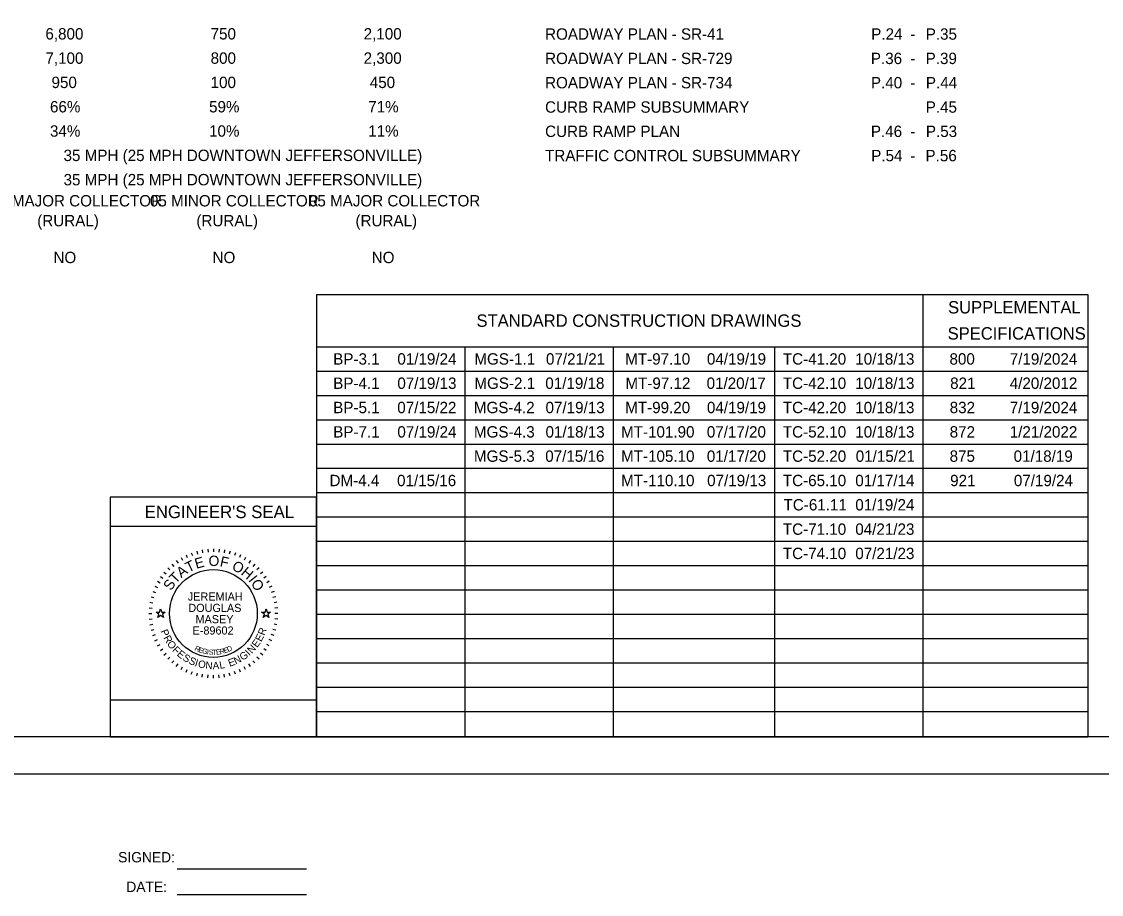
# Model space of a CAD drawing. Extents: x 0 to 34, y -1.6 to 22.
# Drawn here: x 7.84 to 22.48, y -1.63 to 10.19 of the extents above; entities that cross this region are included whole.
import ezdxf

# ---------------------------------------------------------------- set-up
doc = ezdxf.new("R2010")
doc.units = 0
for name, color, linetype in [('SH_Border', 7, 'Continuous'), ('SH_Cut_Line', 7, 'Continuous'), ('SH_Data', 7, 'Continuous'), ('SH_Text', 7, 'Continuous')]:
    doc.layers.add(name, color=color, linetype=linetype)

msp = doc.modelspace()

# ---------------------------------------------------------------- linework, layer by layer
at = {"layer": 'SH_Border'}
msp.add_lwpolyline([(1.5, 21.5), (33.5, 21.5), (33.5, 0.5), (1.5, 0.5)], close=True, dxfattribs=at)
at = {"layer": 'SH_Cut_Line'}
msp.add_lwpolyline([(0, 0), (34, 0), (34, 22), (0, 22)], close=True, dxfattribs=at)
at = {"layer": 'SH_Data'}
for p, q in [((11.844, 3.75), (9.044, 3.75)), ((9.044, 3.75), (9.044, 0.5)), ((11.844, 0.5), (11.844, 3.75)), ((11.844, 3.35), (9.044, 3.35)), ((10.007, 2.931), (10.027, 2.896)), ((10.075, 2.966), (10.091, 2.93)), ((10.145, 2.995), (10.159, 2.957)), ((10.218, 3.018), (10.228, 2.979)), ((10.292, 3.034), (10.299, 2.995)), ((10.368, 3.044), (10.372, 3.005)), ((10.444, 3.048), (10.444, 3.008)), ((10.521, 3.044), (10.517, 3.005)), ((10.596, 3.034), (10.589, 2.995)), ((10.671, 3.018), (10.66, 2.979)), ((10.744, 2.995), (10.73, 2.957)), ((10.814, 2.966), (10.797, 2.93)), ((10.882, 2.931), (10.862, 2.896)), ((9.826, 2.792), (9.854, 2.763)), ((9.882, 2.843), (9.908, 2.812)), ((9.942, 2.89), (9.965, 2.857)), ((10.946, 2.89), (10.923, 2.857)), ((11.007, 2.843), (10.981, 2.812)), ((11.063, 2.792), (11.035, 2.763)), ((9.728, 2.675), (9.76, 2.652)), ((9.774, 2.735), (9.805, 2.71)), ((11.115, 2.735), (11.084, 2.71)), ((11.161, 2.675), (11.128, 2.652)), ((9.651, 2.543), (9.688, 2.526)), ((9.687, 2.61), (9.721, 2.59)), ((11.202, 2.61), (11.168, 2.59)), ((11.237, 2.543), (11.201, 2.526)), ((9.599, 2.399), (9.638, 2.389)), ((9.622, 2.472), (9.66, 2.458)), ((11.267, 2.472), (11.229, 2.458)), ((11.29, 2.399), (11.251, 2.389)), ((9.573, 2.249), (9.613, 2.246)), ((9.583, 2.325), (9.622, 2.318)), ((11.306, 2.325), (11.267, 2.318)), ((11.316, 2.249), (11.276, 2.246)), ((9.569, 2.173), (9.609, 2.173)), ((9.573, 2.097), (9.613, 2.1)), ((11.316, 2.097), (11.276, 2.1)), ((11.319, 2.173), (11.279, 2.173)), ((9.583, 2.021), (9.622, 2.028)), ((9.599, 1.946), (9.638, 1.957)), ((11.29, 1.946), (11.251, 1.957)), ((11.306, 2.021), (11.267, 2.028)), ((9.622, 1.874), (9.66, 1.887)), ((9.651, 1.803), (9.688, 1.82)), ((11.237, 1.803), (11.201, 1.82)), ((11.267, 1.874), (11.229, 1.887)), ((9.687, 1.735), (9.721, 1.755)), ((9.728, 1.671), (9.76, 1.694)), ((9.774, 1.61), (9.805, 1.636)), ((11.115, 1.61), (11.084, 1.636)), ((11.161, 1.671), (11.128, 1.694)), ((11.202, 1.735), (11.168, 1.755)), ((9.826, 1.554), (9.854, 1.582)), ((9.882, 1.503), (9.908, 1.533)), ((9.942, 1.456), (9.965, 1.489)), ((10.946, 1.456), (10.923, 1.489)), ((11.007, 1.503), (10.981, 1.533)), ((11.063, 1.554), (11.035, 1.582)), ((10.007, 1.415), (10.027, 1.45)), ((10.075, 1.38), (10.091, 1.416)), ((10.145, 1.351), (10.159, 1.388)), ((10.218, 1.328), (10.228, 1.366)), ((10.292, 1.311), (10.299, 1.35)), ((10.368, 1.301), (10.372, 1.341)), ((10.444, 1.298), (10.444, 1.338)), ((10.521, 1.301), (10.517, 1.341)), ((10.596, 1.311), (10.589, 1.35)), ((10.671, 1.328), (10.66, 1.366)), ((10.744, 1.351), (10.73, 1.388)), ((10.814, 1.38), (10.797, 1.416)), ((10.882, 1.415), (10.862, 1.45)), ((11.844, 0.5), (9.044, 0.5))]:
    msp.add_line(p, q, dxfattribs=at)
msp.add_lwpolyline([(11.844, 0.5), (11.844, 1), (9.044, 1), (9.044, 0.5)], close=True, dxfattribs=at)
msp.add_circle((10.444, 2.173), 0.595, dxfattribs=at)
at = {"layer": 'SH_Text'}
for p, q in [((11.844, 6.495), (22.303, 6.495)), ((11.844, 6.495), (11.844, 0.5)), ((20.063, 6.495), (20.063, 0.5)), ((22.303, 6.495), (22.303, 0.5)), ((11.844, 5.787), (22.303, 5.787)), ((13.854, 5.787), (13.854, 0.5)), ((15.863, 5.787), (15.863, 0.5)), ((18.054, 5.787), (18.054, 0.5)), ((11.844, 5.458), (22.303, 5.458)), ((11.844, 5.128), (22.303, 5.128)), ((11.844, 4.799), (22.303, 4.799)), ((11.844, 4.469), (22.303, 4.469)), ((11.844, 4.14), (22.303, 4.14)), ((11.844, 3.811), (22.303, 3.811)), ((11.844, 3.481), (22.303, 3.481)), ((11.844, 3.152), (22.303, 3.152)), ((11.844, 2.822), (22.303, 2.822)), ((11.844, 2.493), (22.303, 2.493)), ((11.844, 2.164), (22.303, 2.164)), ((11.844, 1.834), (22.303, 1.834)), ((11.844, 1.505), (22.303, 1.505)), ((11.844, 1.175), (22.303, 1.175)), ((11.844, 0.846), (22.303, 0.846)), ((11.844, 0.5), (22.303, 0.5)), ((9.955, -1.286), (11.705, -1.286)), ((9.955, -1.633), (11.705, -1.633))]:
    msp.add_line(p, q, dxfattribs=at)
for points in [[(9.668, 2.193), (9.715, 2.193), (9.729, 2.237), (9.744, 2.193), (9.791, 2.193), (9.753, 2.165), (9.767, 2.121), (9.729, 2.148), (9.691, 2.121), (9.706, 2.165)], [(11.098, 2.193), (11.145, 2.193), (11.159, 2.237), (11.174, 2.193), (11.221, 2.193), (11.183, 2.165), (11.197, 2.121), (11.159, 2.148), (11.121, 2.121), (11.136, 2.165)]]:
    msp.add_lwpolyline(points, close=True, dxfattribs=at)

# ---------------------------------------------------------------- texts
at = {"layer": 'SH_Data'}
for s, height, p in [("ENGINEER'S SEAL", 0.17, (9.512, 3.465)), ('JEREMIAH', 0.11, (10.098, 2.348)), ('DOUGLAS', 0.11, (10.105, 2.194)), ('MASEY', 0.11, (10.202, 2.041)), ('E-89602', 0.11, (10.162, 1.888))]:
    msp.add_text(s, height=height, dxfattribs=at).set_placement(p)
for s, height, rotation, p in [('E', 0.14, 15.7571, (10.213, 2.777)), ('O', 0.14, 359.7812, (10.379, 2.817)), ('F', 0.14, 347.4362, (10.525, 2.815)), ('A', 0.14, 36.4747, (10.008, 2.651)), ('T', 0.14, 25.7167, (10.106, 2.725)), ('O', 0.14, 332.2586, (10.684, 2.774)), ('H', 0.14, 319.9136, (10.808, 2.709)), ('T', 0.14, 46.4344, (9.933, 2.569)), ('I', 0.14, 308.367, (10.911, 2.621)), ('S', 0.14, 57.1924, (9.872, 2.474)), ('O', 0.14, 303.1491, (10.947, 2.582)), ('P', 0.1, 291.494, (9.727, 1.935)), ('R', 0.1, 69.2322, (11.136, 1.868)), ('R', 0.1, 298.7311, (9.763, 1.844)), ('O', 0.1, 306.4666, (9.81, 1.761)), ('E', 0.1, 54.758, (11.038, 1.704)), ('E', 0.1, 61.9951, (11.092, 1.783)), ('F', 0.1, 314.7068, (9.879, 1.671)), ('E', 0.1, 321.4393, (9.942, 1.608)), ('S', 0.1, 328.6764, (10.019, 1.548)), ('R', 0.07, 334.487, (10.182, 1.678)), ('E', 0.07, 341.04, (10.235, 1.653)), ('G', 0.07, 347.4752, (10.286, 1.635)), ('I', 0.07, 353.7858, (10.353, 1.62)), ('S', 0.07, 356.8926, (10.38, 1.616)), ('T', 0.07, 3.0061, (10.43, 1.611)), ('E', 0.07, 6.0117, (10.483, 1.614)), ('R', 0.07, 11.9184, (10.537, 1.62)), ('E', 0.07, 17.6836, (10.594, 1.633)), ('D', 0.07, 23.3052, (10.645, 1.65)), ('G', 0.1, 35.0469, (10.842, 1.53)), ('I', 0.1, 43.287, (10.931, 1.594)), ('N', 0.1, 47.0224, (10.965, 1.624)), ('S', 0.1, 335.9134, (10.101, 1.499)), ('I', 0.1, 343.1505, (10.185, 1.462)), ('O', 0.1, 346.8859, (10.228, 1.448)), ('N', 0.1, 355.1261, (10.333, 1.425)), ('A', 0.1, 2.8617, (10.437, 1.416)), ('L', 0.1, 10.0987, (10.534, 1.422)), ('E', 0.1, 20.0742, (10.666, 1.45)), ('N', 0.1, 27.3113, (10.749, 1.48))]:
    msp.add_text(s, height=height, rotation=rotation, dxfattribs=at).set_placement(p)
at = {"layer": 'SH_Text'}
for s, height, p in [('6,800', 0.154, (8.167, 9.95)), ('750', 0.154, (10.407, 9.95)), ('2,100', 0.154, (12.482, 9.95)), ('ROADWAY PLAN - SR-41', 0.154, (14.942, 9.947)), ('P.24', 0.154, (19.364, 9.947)), ('P.35', 0.154, (20.103, 9.947)), ('-', 0.154, (19.895, 9.947)), ('7,100', 0.154, (8.167, 9.621)), ('800', 0.154, (10.407, 9.621)), ('2,300', 0.154, (12.482, 9.621)), ('ROADWAY PLAN - SR-729', 0.154, (14.942, 9.617)), ('P.36', 0.154, (19.359, 9.617)), ('-', 0.154, (19.895, 9.617)), ('P.39', 0.154, (20.102, 9.617)), ('950', 0.154, (8.25, 9.292)), ('100', 0.154, (10.407, 9.292)), ('450', 0.154, (12.565, 9.292)), ('ROADWAY PLAN - SR-734', 0.154, (14.942, 9.288)), ('P.40', 0.154, (19.36, 9.288)), ('P.44', 0.154, (20.105, 9.288)), ('-', 0.154, (19.895, 9.288)), ('66%', 0.154, (8.229, 8.962)), ('59%', 0.154, (10.386, 8.962)), ('71%', 0.154, (12.544, 8.962)), ('CURB RAMP SUBSUMMARY', 0.154, (14.942, 8.958)), ('P.45', 0.154, (20.103, 8.958)), ('34%', 0.154, (8.229, 8.633)), ('10%', 0.154, (10.386, 8.633)), ('11%', 0.154, (12.544, 8.633)), ('CURB RAMP PLAN', 0.154, (14.942, 8.629)), ('P.46', 0.154, (19.359, 8.629)), ('P.53', 0.154, (20.105, 8.629)), ('-', 0.154, (19.895, 8.629)), ('35 MPH (25 MPH DOWNTOWN JEFFERSONVILLE)', 0.154, (8.413, 8.303)), ('TRAFFIC CONTROL SUBSUMMARY', 0.154, (14.942, 8.3)), ('P.54', 0.154, (19.364, 8.3)), ('-', 0.154, (19.895, 8.3)), ('P.56', 0.154, (20.1, 8.3)), ('35 MPH (25 MPH DOWNTOWN JEFFERSONVILLE)', 0.154, (8.413, 7.974)), ('05 MAJOR COLLECTOR ', 0.154, (7.425, 7.688)), ('05 MINOR COLLECTOR ', 0.154, (9.584, 7.688)), ('05 MAJOR COLLECTOR ', 0.154, (11.74, 7.688)), ('(RURAL)', 0.154, (8.056, 7.419)), ('(RURAL)', 0.154, (10.214, 7.419)), ('(RURAL)', 0.154, (12.371, 7.419)), ('NO', 0.154, (8.276, 6.92)), ('NO', 0.154, (10.433, 6.92)), ('NO', 0.154, (12.591, 6.92)), ('SUPPLEMENTAL', 0.168, (20.406, 6.238)), ('STANDARD CONSTRUCTION DRAWINGS', 0.168, (14.012, 6.057)), ('SPECIFICATIONS', 0.168, (20.4, 5.884)), ('BP-3.1', 0.154, (12.069, 5.545)), ('01/19/24', 0.154, (12.939, 5.545)), ('MGS-1.1', 0.154, (13.983, 5.545)), ('07/21/21', 0.154, (14.954, 5.545)), ('MT-97.10', 0.154, (16.028, 5.545)), ('04/19/19', 0.154, (17.136, 5.545)), ('TC-41.20', 0.154, (18.166, 5.545)), ('10/18/13', 0.154, (19.148, 5.545)), ('800', 0.154, (20.425, 5.545)), ('7/19/2024', 0.154, (21.242, 5.545)), ('BP-4.1', 0.154, (12.069, 5.216)), ('07/19/13', 0.154, (12.939, 5.216)), ('MGS-2.1', 0.154, (13.983, 5.216)), ('01/19/18', 0.154, (14.945, 5.216)), ('MT-97.12', 0.154, (16.031, 5.216)), ('01/20/17', 0.154, (17.132, 5.216)), ('TC-42.10', 0.154, (18.166, 5.216)), ('10/18/13', 0.154, (19.148, 5.216)), ('821', 0.154, (20.434, 5.216)), ('4/20/2012', 0.154, (21.242, 5.216)), ('BP-5.1', 0.154, (12.069, 4.887)), ('07/15/22', 0.154, (12.938, 4.887)), ('MGS-4.2', 0.154, (13.976, 4.887)), ('07/19/13', 0.154, (14.948, 4.887)), ('MT-99.20', 0.154, (16.028, 4.887)), ('04/19/19', 0.154, (17.136, 4.887)), ('TC-42.20', 0.154, (18.166, 4.887)), ('10/18/13', 0.154, (19.148, 4.887)), ('832', 0.154, (20.428, 4.887)), ('7/19/2024', 0.154, (21.242, 4.887)), ('BP-7.1', 0.154, (12.069, 4.557)), ('07/19/24', 0.154, (12.939, 4.557)), ('MGS-4.3', 0.154, (13.977, 4.557)), ('01/18/13', 0.154, (14.948, 4.557)), ('MT-101.90', 0.154, (15.972, 4.557)), ('07/17/20', 0.154, (17.135, 4.557)), ('TC-52.10', 0.154, (18.166, 4.557)), ('10/18/13', 0.154, (19.148, 4.557)), ('872', 0.154, (20.428, 4.557)), ('1/21/2022', 0.154, (21.242, 4.557)), ('MGS-5.3', 0.154, (13.977, 4.228)), ('07/15/16', 0.154, (14.944, 4.228)), ('MT-105.10', 0.154, (15.972, 4.228)), ('01/17/20', 0.154, (17.135, 4.228)), ('TC-52.20', 0.154, (18.166, 4.228)), ('01/15/21', 0.154, (19.154, 4.228)), ('875', 0.154, (20.427, 4.228)), ('01/18/19', 0.154, (21.295, 4.228)), ('DM-4.4', 0.154, (12.019, 3.898)), ('01/15/16', 0.154, (12.935, 3.898)), ('MT-110.10', 0.154, (15.972, 3.898)), ('07/19/13', 0.154, (17.139, 3.898)), ('TC-65.10', 0.154, (18.166, 3.898)), ('01/17/14', 0.154, (19.148, 3.898)), ('921', 0.154, (20.434, 3.898)), ('07/19/24', 0.154, (21.298, 3.898)), ('TC-61.11', 0.154, (18.175, 3.569)), ('01/19/24', 0.154, (19.148, 3.569)), ('TC-71.10', 0.154, (18.166, 3.239)), ('04/21/23', 0.154, (19.148, 3.239)), ('TC-74.10', 0.154, (18.166, 2.91)), ('07/21/23', 0.154, (19.148, 2.91)), ('SIGNED:', 0.14, (9.153, -1.199)), ('DATE:', 0.14, (9.264, -1.6))]:
    msp.add_text(s, height=height, dxfattribs=at).set_placement(p)

doc.saveas('drawing.dxf')
